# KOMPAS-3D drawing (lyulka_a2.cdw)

Views: Вид 1, Вид 2, Вид 3, Выносной элемент А, Выносной элемент, Выносной элемент Б
Referenced files in D:\Program Files\ASCON\KOMPAS-3D LT V11\Sys\: Graphic.lcs
Referenced files: Металлоконструкция.cdw
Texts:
  КП.1.О.4054.
  Карта  металлоконструкции
  User
  Noncommercial version
  Текст на чертеже
  Размерные надписи
  Шероховатость
  Линия-выноска #1
  Линия-выноска #2
  Линия-выноска #3
  Отклонения формы и база
  Заголовок таблицы
  Ячейка таблицы
  Стрелка вида
  Обозначение изменения
  Фигурная скобка
  Номер узла
  Марка координационной оси
  VRCB
  Выносная надпись
  Обозначение узла
  Марка/позиционное обозначение с линией-выноской
  Марка/позиционное обозначение на линии
  Марка/позиционное обозначение без линии-выноски
  Эпюра Q, кН
  Эпюра М, кНм
  ГОСТ5264-80-С8
  Уголок 63x40x4-B ГОСТ8510-86 345 ГОСТ19281-89
  Скрытая линия
  Сварные швы
  ГОСТ 15-1932
  ГОСТ 8510-86*
  Карта
  металлоконструкции
  Дружинин
  Реутов
  Фомич
  Капустин
Dimensions and other numbers on the sheet: 7; 0,987; 0,411; 50; 100; 80; 20; 2500; 1700; 1000; 3; 213; 1400; 445; 60; 90; 620; 276; 248; 415; 4; 0,7583; 0,746; 0,6343; 1:14,3; 1; 0; 2; 5; 6; 8; 9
